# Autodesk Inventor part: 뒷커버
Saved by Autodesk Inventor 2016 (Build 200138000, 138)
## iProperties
Created: 2024-08
Part Number: 뒷커버
Material: 일반
Document SubType Name: Modeling
Designer: pc-2
Density: 1 g/cm^3
Appearance: 기본값
Author: jhkim
Sending System: Autodesk Inventor 2025
Preprocessor: ST-DEVELOPER v20
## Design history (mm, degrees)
node "뒷커버1"
node "솔리드2"
node "솔리드1"
